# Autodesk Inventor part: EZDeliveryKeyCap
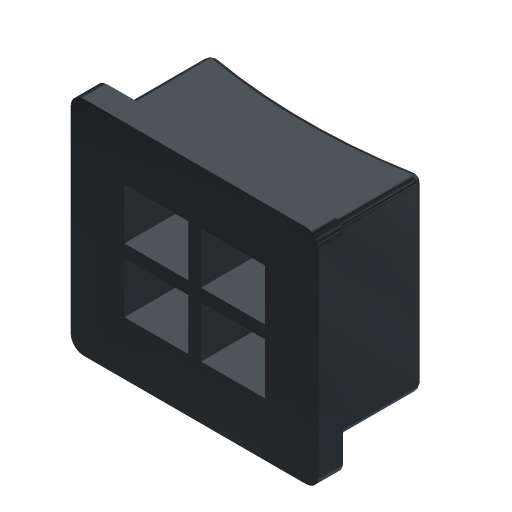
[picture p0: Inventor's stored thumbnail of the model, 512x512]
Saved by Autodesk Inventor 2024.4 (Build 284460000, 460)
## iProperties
Created: 2026-01
Part Number: EZDeliveryKeyCap
Material: Gusseisen, Grau, ASTM A48 Klasse 20
Document SubType Name: Modeling
Designer: offt
Density: 7.3953 g/cm^3
Appearance: Eisen - Grau
Mass: 1.71492 g
Surface Area: 4.39851 cm^2
Volume: 0.231893 cm^3
Author: offt
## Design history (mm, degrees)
sketch "Skizze1"
  geometry: L1 (-13.839, 7.226)-(-5.489, 7.226); L2 (-5.489, 7.226)-(-5.489, 3.326); L3 (-5.489, 3.326)-(-13.839, 3.326); L4 (-13.839, 3.326)-(-13.839, 7.226); A1 r 21.988 centre (-9.664, 28.815) between (-13.839, 7.226) and (-5.489, 7.226); 2 further points
  constraints: 8 end point, 3 point on circle, 2 parallel, 1 centre point, 1 horizontal, 1 midpoint, 1 perpendicular
  dimensions: "d0" = 8.35 distance of L1.start L1.end; "d1" = 3.9 distance of L3.end L1.start; "d2" = 0.4 distance of point (-9.664, 6.826) point (-9.664, 7.226)
extrude "Extrusion1" new body sketch "Skizze1" distance "d3" = 7.35; taper "d4" = 0 deg
fillet "Rundung1" dims "d5" = 0.3
fillet "Rundung2" dims "d6" = 0.3
sketch "Skizze2"
  geometry: L1 (-0.3, 0.3)-(-0.3, 7.05) reference; L2 (0, 7.35)-(7.75, 7.35) reference; L3 (8.05, 7.05)-(8.05, 0.3) reference; L4 (7.75, 0)-(0, 0) reference; L5 (-0.975, 8.025)-(8.725, 8.025); L6 (8.725, 8.025)-(8.725, -0.675); L7 (8.725, -0.675)-(-0.975, -0.675); L8 (-0.975, -0.675)-(-0.975, 8.025); A1 r 0.3 centre (0, 0.3) between (-0.3, 0.3) and (0, 0) reference; A2 r 0.3 centre (0, 7.05) between (0, 7.35) and (-0.3, 7.05) reference; A3 r 0.3 centre (7.75, 7.05) between (8.05, 7.05) and (7.75, 7.35) reference; A4 r 0.3 centre (7.75, 0.3) between (7.75, 0) and (8.05, 0.3) reference; 1 further point
  constraints: 8 end point, 2 parallel, 1 horizontal, 1 perpendicular
  dimensions: "d7" = 9.7 distance of L5.start L5.end; "d8" = 8.7 distance of L7.end L5.start; "d9" = 7.35 distance between parallel lines of L4 L2 (derived); "d10" = 8.35 distance between parallel lines of L3 L1 (derived); "d11" = 0.675 distance between parallel lines of L8 L1 (= -0.5 x d10 + 0.5 x d7); "d12" = 0.675 distance between parallel lines of L5 L2 (= -0.5 x d9 + 0.5 x d8)
extrude "Extrusion2" join sketch "Skizze2" distance "d13" = 0.95; taper "d14" = 0 deg
fillet "Rundung3" dims "d15" = 0.5
sketch "Skizze3"
  geometry: L1 (8.225, -0.675)-(-0.475, -0.675) reference; L2 (-0.975, -0.175)-(-0.975, 7.525) reference; L3 (-0.475, 8.025)-(8.225, 8.025) reference; L4 (8.725, 7.525)-(8.725, -0.175) reference; L5 (1.125, 5.925)-(6.625, 5.925); L6 (6.625, 5.925)-(6.625, 1.425); L7 (6.625, 1.425)-(1.125, 1.425); L8 (1.125, 1.425)-(1.125, 5.925); L9 (3.625, 5.925)-(4.125, 5.925); L10 (4.125, 5.925)-(4.125, 1.425); L11 (4.125, 1.425)-(3.625, 1.425); L12 (3.625, 1.425)-(3.625, 5.925); L13 (1.125, 3.925)-(6.625, 3.925); L14 (6.625, 3.925)-(6.625, 3.425); L15 (6.625, 3.425)-(1.125, 3.425); L16 (1.125, 3.425)-(1.125, 3.925); A1 r 0.5 centre (8.225, -0.175) between (8.225, -0.675) and (8.725, -0.175) reference; A2 r 0.5 centre (-0.475, -0.175) between (-0.975, -0.175) and (-0.475, -0.675) reference; A3 r 0.5 centre (-0.475, 7.525) between (-0.475, 8.025) and (-0.975, 7.525) reference; A4 r 0.5 centre (8.225, 7.525) between (8.725, 7.525) and (8.225, 8.025) reference; 10 further points
  constraints: 24 end point, 6 parallel, 4 point on line, 3 horizontal, 3 perpendicular, 1 midpoint
  dimensions: "d16" = 5.5 distance of L5.start L5.end; "d17" = 4.5 distance of L7.end L5.start; "d18" = 8.7 distance from line of L1 point (3.875, 8.025) (derived); "d19" = 9.7 distance between parallel lines of L4 L2 (derived); "d20" = 2.1 distance between parallel lines of L4 L6 (= -0.5 x d16 + 0.5 x d19); "d21" = 2.1 distance between parallel lines of L3 L5 (= -0.5 x d17 + 0.5 x d18); "d22" = 2 distance between parallel lines of L13 L5; "d23" = 2 distance between parallel lines of L15 L7; "d24" = 2.5 distance between parallel lines of L8 L12; "d25" = 2.5 distance between parallel lines of L6 L10
extrude "Extrusion3" cut sketch "Skizze3" distance "d26" = 3.5; taper "d27" = 0 deg
node "Volumenkörper1"
node "Volumenkörper"
node "Flächenkörper"
node "Schnittkanten projizieren1"
node "Schnittkanten projizieren2"
